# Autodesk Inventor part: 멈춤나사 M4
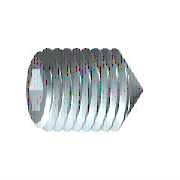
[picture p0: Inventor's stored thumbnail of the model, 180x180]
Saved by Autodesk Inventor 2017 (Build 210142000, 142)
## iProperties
Created: 2012-02
Part Number: 멈춤나사 M4
Material: 강철, 연강
Document SubType Name: Modeling
Standard: JIS B 1177 원추점
Designer: mdu-01
Standards Organization: JIS
Language: ko-KR
Size Designation: M4 x 10
Categories: <MemberInstance><Categories><Category DisplayName="조임쇠" InternalName="e4da775c-781d-43d5-af7c-5136215cf5a6" Mnemonic="FSTN"><Category DisplayName="볼트" InternalN
Density: 1 g/cm^3
Appearance: 강철
IsCustomPart: 1
Author: mdu-01
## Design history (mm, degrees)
sketch "스케치1"
  geometry: L1 (0, 0)-(6.833, 0); L2 (10, 1.155)-(10, 2); L3 (10, 2)-(0, 2); L4 (10, 1.155)-(7.5, 1.155); L5 (7.5, 1.155)-(6.833, 0); L6 (0, -0.4)-(0, 2.4) reference; L7 (0, 2)-(0, 0)
  constraints: 13 end point, 3 parallel, 1 collinear, 1 perpendicular, 1 point on line
  dimensions: "d0" = 2.5 distance of L2.start L4.end (= INTI); "d1" = 60 deg angle of L5 L1; "d2" = 4 diameter of L3 L1 (= NND); "d3" = 2.3094 diameter of L4 L1 (= 1.1547 x SW); "d5" = 10 distance from line of L2 L3.end (= NLG)
revolve "본체" sketch "스케치1" stored, may be unused: angle "d6" = 90 deg
sketch "스케치2"
  geometry: L1 (-0.577, 1)-(0.577, 1); L2 (0.577, 1)-(1.155, 0); L3 (1.155, 0)-(0.577, -1); L4 (0.577, -1)-(-0.577, -1); L5 (-0.577, -1)-(-1.155, 0); L6 (-1.155, 0)-(-0.577, 1); 3 further points
  constraints: 12 end point, 1 coincident, 1 horizontal, 13 other
extrude "슬롯" join sketch "스케치2" taper "d7" = 0 deg; stored distance "d21" = 10
workaxis "Work Axis1"
workplane "Work Plane1"
body "Solid1"
feature "스레드" dims "d12" = 10 (= NLG), "d13" = 0
chamfer "모따기1" distance "d8" = 1.03923 (computed from NND, SPD, FAWI); stored, may be unused: angle "d9" = 60 deg (= FAWI), second distance "d34" = 1.03923 (computed from NND, SPD, FAWI)
chamfer "모따기2" distance "d10" = 0.42941 (= -0.5 x GD1 + 0.5 x NND); stored, may be unused: angle "d11" = 60 deg (= FAWI), second distance "d35" = 0.42941 (= -0.5 x GD1 + 0.5 x NND)
other parameters: "NND" = 4 [user parameter; used in 5 equation terms], "NLG" = 10 [user parameter; used in 2 equation terms], "INTI" = 2.5 [user parameter; used in 1 equation term], "FAWI" = 60 deg [user parameter; used in 4 equation terms], "SW" = 2 [user parameter; used in 2 equation terms], "GD1" = 3.14117 (= THREADDIA - 1.2269 x PTC) [user parameter; used in 2 equation terms], "d4" = 0, "FAWI1" = 45 deg [user parameter], "SPD" = 0.4 [user parameter; used in 2 equation terms], "d36" = 0, "d37" = 0, "GUL" = 0.42941 (= 0.61345 x PTC) [user parameter], "TPU" = 14.28571 (computed from PTC) [user parameter], "TOA" = 30 deg [user parameter], "THREADDIA" = 4 [user parameter; used in 1 equation term], "PTC" = 0.7 [user parameter; used in 4 equation terms], "GAL" = 0.42941 (= 0.61345 x PTC) [user parameter], "E0" = 2.31 (= 1.155 x SW) [user parameter]
